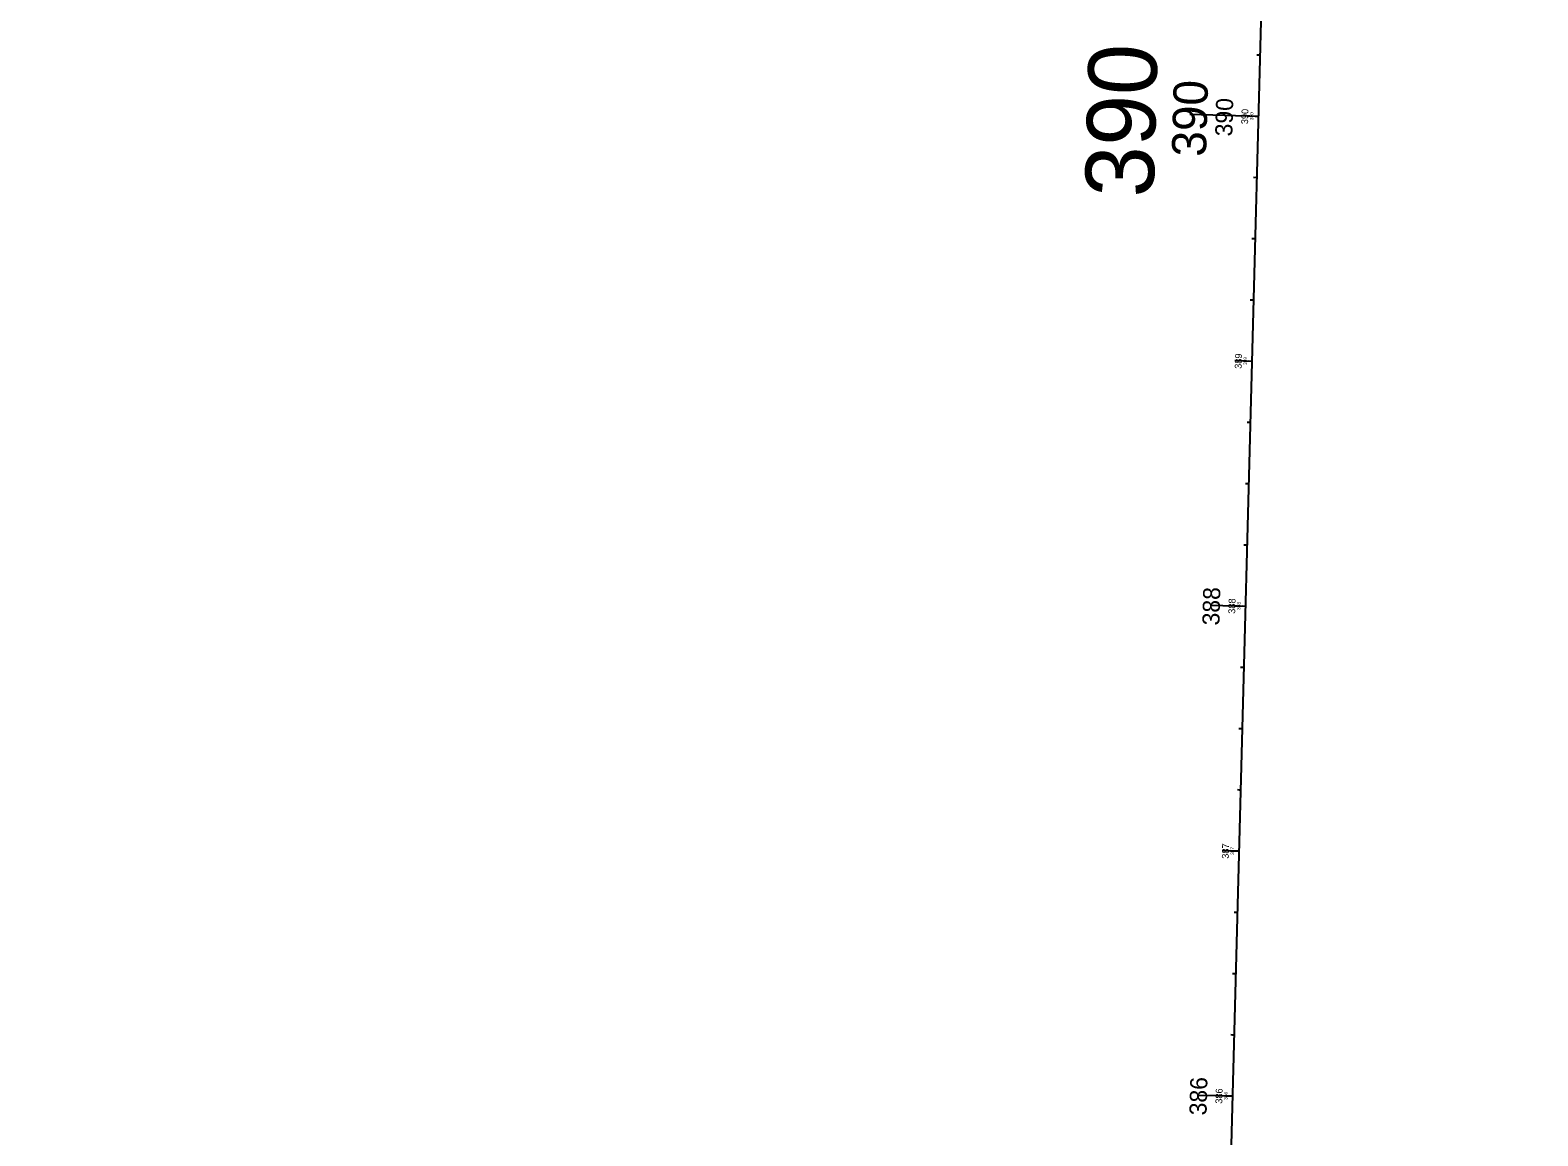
# Model space of a CAD drawing. Extents: x 564646 to 607088, y 225853 to 261760.
# Drawn here: x 598401 to 599017, y 252777 to 253228 of the extents above; entities that cross this region are included whole.
import ezdxf

# ---------------------------------------------------------------- set-up
doc = ezdxf.new("R2010")
doc.units = 0
for name, color, linetype in [('B_CONC_HIDDEN_LT', 7, 'Continuous'), ('E-Property Lines', 7, 'Continuous'), ('E_ALI_100', 7, 'Continuous'), ('E_RW_CorporateLimits', 7, 'Continuous'), ('E_RW_EasementUtility_Text', 7, 'Continuous'), ('EMCS_SURVEY_PT CODES', 7, 'Continuous'), ('EMCS_SURVEY_PT ELEV', 7, 'Continuous'), ('Level 33', 7, 'Continuous'), ('P-Easements Floodplain', 7, 'Continuous'), ('P_ALI_100_Tic', 7, 'Continuous'), ('P_ALI_20', 7, 'Continuous'), ('P_RW_EasementPerm', 7, 'Continuous'), ('P_RW_EasementTemp', 7, 'Continuous'), ('P_RW_PropertyConnector', 7, 'Continuous'), ('P_RW_Proposed', 7, 'Continuous')]:
    doc.layers.add(name, color=color, linetype=linetype)

msp = doc.modelspace()

# ---------------------------------------------------------------- linework, layer by layer
at = {"layer": 'B_CONC_HIDDEN_LT'}
msp.add_line((598400.93, 234167.82), (599016.61, 257518.82), dxfattribs=at)
at = {"layer": 'E_ALI_100'}
for points in [[(598901.81, 253217.97), (598903.21, 253217.94)], [(598899.75, 253193.02), (598902.55, 253192.94)], [(598900.49, 253167.99), (598901.89, 253167.95)], [(598899.84, 253143), (598901.23, 253142.96)], [(598899.18, 253118.01), (598900.58, 253117.97)], [(598897.12, 253093.05), (598899.92, 253092.98)], [(598897.86, 253068.02), (598899.26, 253067.99)], [(598897.2, 253043.03), (598898.6, 253043)], [(598896.54, 253018.04), (598897.94, 253018)], [(598894.48, 252993.09), (598897.28, 252993.01)], [(598895.22, 252968.06), (598896.62, 252968.02)], [(598894.56, 252943.07), (598895.96, 252943.03)], [(598893.91, 252918.08), (598895.3, 252918.04)], [(598891.85, 252893.12), (598894.65, 252893.05)], [(598892.59, 252868.09), (598893.99, 252868.06)], [(598891.93, 252843.1), (598893.33, 252843.07)], [(598891.27, 252818.11), (598892.67, 252818.07)], [(598889.21, 252793.16), (598892.01, 252793.08)]]:
    msp.add_lwpolyline(points, dxfattribs=at)
at = {"layer": 'EMCS_SURVEY_PT CODES'}
msp.add_line((598400.93, 234167.82), (599016.61, 257518.82), dxfattribs=at)
at = {"layer": 'EMCS_SURVEY_PT ELEV'}
msp.add_line((598400.93, 234167.82), (599016.61, 257518.82), dxfattribs=at)
msp.add_line((598400.93, 234167.82), (599016.61, 257518.82), dxfattribs=at)
at = {"layer": 'Level 33'}
for points in [[(598902.51, 253217.95), (598903.21, 253217.94)], [(598901.15, 253192.98), (598902.55, 253192.94)], [(598901.19, 253167.97), (598901.89, 253167.95)], [(598900.54, 253142.98), (598901.23, 253142.96)], [(598899.88, 253117.99), (598900.58, 253117.97)], [(598898.52, 253093.02), (598899.92, 253092.98)], [(598898.56, 253068.01), (598899.26, 253067.99)], [(598897.9, 253043.01), (598898.6, 253043)], [(598897.24, 253018.02), (598897.94, 253018)], [(598895.88, 252993.05), (598897.28, 252993.01)], [(598895.92, 252968.04), (598896.62, 252968.02)], [(598895.26, 252943.05), (598895.96, 252943.03)], [(598894.6, 252918.06), (598895.3, 252918.04)], [(598893.25, 252893.09), (598894.65, 252893.05)], [(598893.29, 252868.08), (598893.99, 252868.06)], [(598892.63, 252843.08), (598893.33, 252843.07)], [(598891.97, 252818.09), (598892.67, 252818.07)], [(598890.61, 252793.12), (598892.01, 252793.08)]]:
    msp.add_lwpolyline(points, dxfattribs=at)
at = {"layer": 'P-Easements Floodplain'}
msp.add_line((598400.93, 234167.82), (599016.61, 257518.82), dxfattribs=at)
at = {"layer": 'P_ALI_100_Tic'}
for points in [[(598874.56, 253193.68), (598902.55, 253192.94)], [(598883.29, 252993.38), (598897.28, 252993.01)], [(598878.01, 252793.45), (598892.01, 252793.08)]]:
    msp.add_lwpolyline(points, dxfattribs=at)
at = {"layer": 'P_ALI_20'}
for points in [[(598888.56, 253193.31), (598902.55, 253192.94)], [(598892.92, 253093.16), (598899.92, 253092.98)], [(598890.28, 252993.2), (598897.28, 252993.01)], [(598887.65, 252893.23), (598894.65, 252893.05)], [(598885.01, 252793.27), (598892.01, 252793.08)]]:
    msp.add_lwpolyline(points, dxfattribs=at)
at = {"layer": 'P_RW_EasementPerm'}
for points in [[(598895.56, 253193.13), (598902.55, 253192.94)], [(598896.42, 253093.07), (598899.92, 253092.98)], [(598890.28, 252993.2), (598897.28, 252993.01)], [(598891.15, 252893.14), (598894.65, 252893.05)], [(598885.01, 252793.27), (598892.01, 252793.08)]]:
    msp.add_lwpolyline(points, dxfattribs=at)
at = {"layer": 'P_RW_EasementTemp'}
msp.add_line((598400.93, 234167.82), (599016.61, 257518.82), dxfattribs=at)
at = {"layer": 'P_RW_PropertyConnector'}
msp.add_line((598400.93, 234167.82), (599016.61, 257518.82), dxfattribs=at)

# ---------------------------------------------------------------- texts
for s, p in [('390', (598898.26, 253189.61)), ('389', (598895.63, 253089.78)), ('388', (598893, 252989.82)), ('387', (598890.36, 252889.85)), ('386', (598887.72, 252789.89))]:
    msp.add_text(s, height=2.8, rotation=88.48966).set_placement(p)
at = {"layer": 'E-Property Lines'}
msp.add_text('390', height=28, rotation=88.48966, dxfattribs=at).set_placement((598859.66, 253159.56))
at = {"layer": 'E_RW_CorporateLimits'}
msp.add_text('390', height=14, rotation=88.48966, dxfattribs=at).set_placement((598881.11, 253176.25))
at = {"layer": 'E_RW_EasementUtility_Text'}
for s, p in [('390', (598900.41, 253191.27)), ('389', (598897.77, 253091.38)), ('388', (598895.14, 252991.42)), ('387', (598892.5, 252891.45)), ('386', (598889.87, 252791.49))]:
    msp.add_text(s, height=1.4, rotation=88.48966, dxfattribs=at).set_placement(p)
at = {"layer": 'P_RW_Proposed'}
for s, p in [('390', (598891.83, 253184.6)), ('388', (598886.57, 252985.03)), ('386', (598881.3, 252785.1))]:
    msp.add_text(s, height=7, rotation=88.48966, dxfattribs=at).set_placement(p)

doc.saveas('drawing.dxf')
